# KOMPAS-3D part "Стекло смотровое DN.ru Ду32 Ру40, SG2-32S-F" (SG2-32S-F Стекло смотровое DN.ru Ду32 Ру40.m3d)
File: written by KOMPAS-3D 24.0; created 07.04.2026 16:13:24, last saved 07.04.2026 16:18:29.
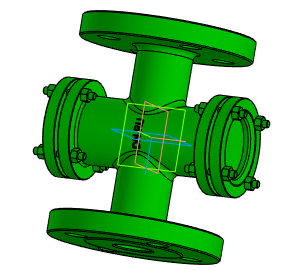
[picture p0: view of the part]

Document properties: Автор: Main; Полное имя файла: D:\DN.ru Аутсерс\Стекло смотровое DN.ru\SG2-32S-F Стекло смотровое DN.ru Ду32 Ру40\SG2-32S-F Стекло смотровое DN.ru Ду32 Ру40.m3d

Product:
- Body: Тело 1  | qty 1
    Масса: 6.03947
- Part/product: Стекло смотровое DN.ru Ду32 Ру40  | designation SG2-32S-F
    Масса: 6.2
    Раздел спецификации: Прочие изделия
    Примечание: D500-00106

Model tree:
1. Операция без истории:1

Expressions: SG2-32S-F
